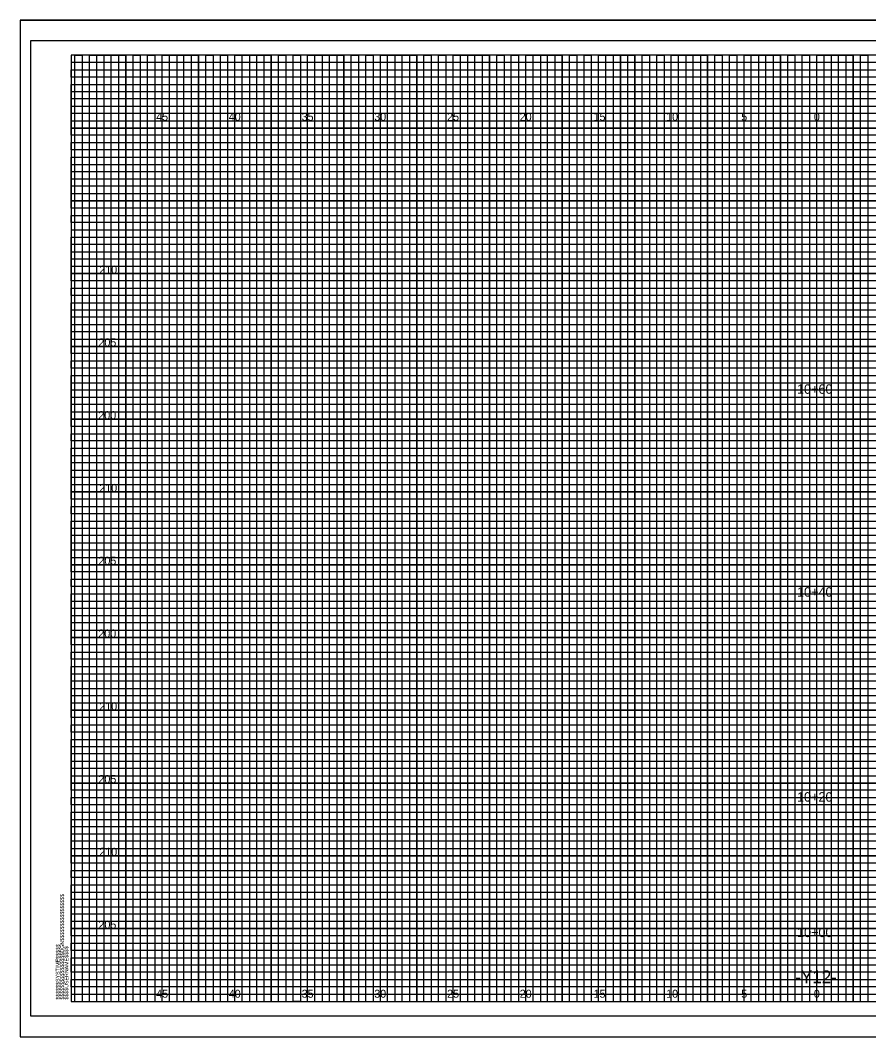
# Model space of a CAD drawing. Extents: x -4 to 103, y -2 to 138.
# Drawn here: x -3.5 to 54.8, y -2.4 to 67.4 of the extents above; entities that cross this region are included whole.
import ezdxf

# ---------------------------------------------------------------- set-up
doc = ezdxf.new("R2010")
doc.units = 0
for name, color, linetype in [('Exist XS Ground Line', 7, 'Continuous'), ('Old_Level_10', 7, 'Continuous'), ('Old_Level_16', 7, 'Continuous'), ('Old_Level_3', 7, 'Continuous'), ('Old_Level_5', 7, 'Continuous'), ('Old_Level_8', 7, 'Continuous'), ('Prop XS Dump Level', 7, 'Continuous'), ('Prop XS Elevation Labels', 7, 'Continuous'), ('Prop XS EOT Tick Mark', 7, 'Continuous'), ('Prop XS Finish Grade', 7, 'Continuous'), ('Prop XS Suitable Common Exc Shape', 7, 'Continuous')]:
    doc.layers.add(name, color=color, linetype=linetype)

msp = doc.modelspace()

# ---------------------------------------------------------------- linework, layer by layer
at = {"layer": 'Exist XS Ground Line'}
msp.add_lwpolyline([(103, 66), (-2.8, 66), (-2.8, -1), (103, -1)], close=True, dxfattribs=at)
at = {"layer": 'Old_Level_10'}
for p, q in [((1.25, 0), (1.25, 65)), ((3.75, 0), (3.75, 65)), ((6.25, 0), (6.25, 65)), ((8.75, 0), (8.75, 65)), ((11.25, 0), (11.25, 65)), ((13.75, 0), (13.75, 65)), ((16.25, 0), (16.25, 65)), ((18.75, 0), (18.75, 65)), ((21.25, 0), (21.25, 65)), ((23.75, 0), (23.75, 65)), ((26.25, 0), (26.25, 65)), ((28.75, 0), (28.75, 65)), ((31.25, 0), (31.25, 65)), ((33.75, 0), (33.75, 65)), ((36.25, 0), (36.25, 65)), ((38.75, 0), (38.75, 65)), ((41.25, 0), (41.25, 65)), ((43.75, 0), (43.75, 65)), ((46.25, 0), (46.25, 65)), ((48.75, 0), (48.75, 65)), ((51.25, 0), (51.25, 65)), ((53.75, 0), (53.75, 65)), ((0, 62.5), (74.25, 62.5)), ((0, 60), (102.5, 60)), ((0, 57.5), (102.5, 57.5)), ((0, 55), (102.5, 55)), ((0, 52.5), (102.5, 52.5)), ((0, 50), (102.5, 50)), ((0, 47.5), (102.5, 47.5)), ((0, 45), (102.5, 45)), ((0, 42.5), (102.5, 42.5)), ((0, 40), (102.5, 40)), ((0, 37.5), (102.5, 37.5)), ((0, 35), (102.5, 35)), ((0, 32.5), (102.5, 32.5)), ((0, 30), (102.5, 30)), ((0, 27.5), (102.5, 27.5)), ((0, 25), (102.5, 25)), ((0, 22.5), (102.5, 22.5)), ((0, 20), (102.5, 20)), ((0, 17.5), (102.5, 17.5)), ((0, 15), (102.5, 15)), ((0, 12.5), (102.5, 12.5)), ((0, 10), (102.5, 10)), ((0, 7.5), (102.5, 7.5)), ((0, 5), (102.5, 5)), ((0, 2.5), (102.5, 2.5))]:
    msp.add_line(p, q, dxfattribs=at)
at = {"layer": 'Old_Level_3'}
for p, q in [((-3.5, 67.4), (103.4, 67.4)), ((-3.5, 67.4), (-3.5, -2.425)), ((-3.5, -2.425), (103.4, -2.425))]:
    msp.add_line(p, q, dxfattribs=at)
at = {"layer": 'Old_Level_5'}
msp.add_lwpolyline([(103.4, 67.4), (-3.5, 67.4), (-3.5, -2.425), (103.4, -2.425)], close=True, dxfattribs=at)
at = {"layer": 'Old_Level_8'}
for points in [[(1.25, 0), (1.25, 65), (3.75, 65), (3.75, 0), (6.25, 0), (6.25, 65), (8.75, 65), (8.75, 0), (11.25, 0), (11.25, 65), (13.75, 65), (13.75, 0), (16.25, 0), (16.25, 65), (18.75, 65), (18.75, 0), (21.25, 0), (21.25, 65), (23.75, 65), (23.75, 0), (26.25, 0), (26.25, 65), (28.75, 65), (28.75, 0), (31.25, 0), (31.25, 65), (33.75, 65), (33.75, 0), (36.25, 0), (36.25, 65), (38.75, 65), (38.75, 0), (41.25, 0), (41.25, 65), (43.75, 65), (43.75, 0), (46.25, 0), (46.25, 65), (48.75, 65), (48.75, 0), (51.25, 0), (51.25, 65), (53.75, 65), (53.75, 0)], [(102.5, 60), (0, 60), (0, 62.5), (74.25, 62.5)], [(102.5, 55), (0, 55), (0, 57.5), (102.5, 57.5)], [(102.5, 50), (0, 50), (0, 52.5), (102.5, 52.5)], [(102.5, 45), (0, 45), (0, 47.5), (102.5, 47.5)], [(102.5, 40), (0, 40), (0, 42.5), (102.5, 42.5)], [(102.5, 35), (0, 35), (0, 37.5), (102.5, 37.5)], [(102.5, 30), (0, 30), (0, 32.5), (102.5, 32.5)], [(102.5, 25), (0, 25), (0, 27.5), (102.5, 27.5)], [(102.5, 20), (0, 20), (0, 22.5), (102.5, 22.5)], [(102.5, 15), (0, 15), (0, 17.5), (102.5, 17.5)], [(102.5, 10), (0, 10), (0, 12.5), (102.5, 12.5)], [(102.5, 5), (0, 5), (0, 7.5), (102.5, 7.5)], [(0, 2.5), (102.5, 2.5)]]:
    msp.add_lwpolyline(points, dxfattribs=at)
at = {"layer": 'Prop XS Elevation Labels'}
msp.add_lwpolyline([(102.5, 65), (0, 65), (0, 0), (102.5, 0)], close=True, dxfattribs=at)
at = {"layer": 'Prop XS Finish Grade'}
for points in [[(0.25, 0), (0.25, 65), (0.75, 65), (0.75, 0), (1.75, 0), (1.75, 65), (2.25, 65), (2.25, 0), (2.75, 0), (2.75, 65), (3.25, 65), (3.25, 0), (4.25, 0), (4.25, 65), (4.75, 65), (4.75, 0), (5.25, 0), (5.25, 65), (5.75, 65), (5.75, 0), (6.75, 0), (6.75, 65), (7.25, 65), (7.25, 0), (7.75, 0), (7.75, 65), (8.25, 65), (8.25, 0), (9.25, 0), (9.25, 65), (9.75, 65), (9.75, 0), (10.25, 0), (10.25, 65), (10.75, 65), (10.75, 0), (11.75, 0), (11.75, 65), (12.25, 65), (12.25, 0), (12.75, 0), (12.75, 65), (13.25, 65), (13.25, 0), (14.25, 0), (14.25, 65), (14.75, 65), (14.75, 0), (15.75, 0), (15.25, 0), (15.25, 65), (15.75, 65), (15.75, 0), (16.75, 0), (16.75, 65), (17.25, 65), (17.25, 0), (17.75, 0), (17.75, 65), (18.25, 65), (18.25, 0), (19.25, 0), (19.25, 65), (19.75, 65), (19.75, 0), (20.25, 0), (20.25, 65), (20.75, 65), (20.75, 0), (21.75, 0), (21.75, 65), (22.25, 65), (22.25, 0), (22.75, 0), (22.75, 65), (23.25, 65), (23.25, 0), (24.25, 0), (24.25, 65), (24.75, 65), (24.75, 0), (25.25, 0), (25.25, 65), (25.75, 65), (25.75, 0), (26.75, 0), (26.75, 65), (27.25, 65), (27.25, 0), (27.75, 0), (27.75, 65), (28.25, 65), (28.25, 0), (29.25, 0), (29.25, 65), (29.75, 65), (29.75, 0), (30.25, 0), (30.25, 65), (30.75, 65), (30.75, 0)], [(30.75, 0), (31.75, 0), (31.75, 65), (32.25, 65), (32.25, 0), (32.75, 0), (32.75, 65), (33.25, 65), (33.25, 0), (34.25, 0), (34.25, 65), (34.75, 65), (34.75, 0), (35.25, 0), (35.25, 65), (35.75, 65), (35.75, 0), (36.75, 0), (36.75, 65), (37.25, 65), (37.25, 0), (37.75, 0), (37.75, 65), (37.75, 0)], [(38.25, 65), (38.25, 0), (39.25, 0), (39.25, 65), (39.75, 65), (39.75, 0), (40.25, 0), (40.25, 65), (40.75, 65), (40.75, 0), (41.75, 0), (41.75, 65), (42.25, 65), (42.25, 0), (42.75, 0), (42.75, 65), (43.25, 65), (43.25, 0), (43.75, 0), (44.25, 0), (44.25, 65), (44.75, 65), (44.75, 0), (45.25, 0), (45.25, 65), (45.75, 65), (45.75, 0), (46.75, 0), (46.75, 65), (47.25, 65), (47.25, 0), (47.75, 0), (47.75, 65), (48.25, 65), (48.25, 0), (49.25, 0), (49.25, 65), (49.75, 65), (49.75, 0), (50.25, 0), (50.25, 65), (50.75, 65), (50.75, 0), (51.75, 0), (51.75, 65), (52.25, 65), (52.25, 0), (52.75, 0), (52.75, 65), (53.25, 65), (53.25, 0), (54.25, 0), (54.25, 65), (54.75, 65), (54.75, 0), (55.25, 0)], [(0, 62), (0, 63), (74.25, 63), (74.25, 63.5), (0, 63.5), (0, 64), (74.25, 64), (74.25, 64.5), (0, 64.5)], [(102.5, 62), (0, 62)], [(102.5, 61), (0, 61), (0, 61.5), (102.5, 61.5)], [(102.5, 59.5), (0, 59.5), (0, 60.5), (102.5, 60.5)], [(102.5, 58.5), (0, 58.5), (0, 59), (102.5, 59)], [(102.5, 57), (0, 57), (0, 58), (102.5, 58)], [(102.5, 56), (0, 56), (0, 56.5), (102.5, 56.5)], [(102.5, 54.5), (0, 54.5), (0, 55.5), (102.5, 55.5)], [(102.5, 53.5), (0, 53.5), (0, 54), (102.5, 54)], [(0, 53), (102.5, 53)], [(102.5, 52), (0, 52)], [(102.5, 51), (0, 51), (0, 51.5), (102.5, 51.5)], [(102.5, 49.5), (0, 49.5), (0, 50.5), (102.5, 50.5)], [(102.5, 48.5), (0, 48.5), (0, 49), (102.5, 49)], [(102.5, 47), (0, 47), (0, 48), (102.5, 48)], [(102.5, 46), (0, 46), (0, 46.5), (102.5, 46.5)], [(102.5, 44.5), (0, 44.5), (0, 45.5), (102.5, 45.5)], [(102.5, 43.5), (0, 43.5), (0, 44), (102.5, 44)], [(102.5, 42), (0, 42), (0, 43), (102.5, 43)], [(102.5, 41), (0, 41), (0, 41.5), (102.5, 41.5)], [(102.5, 39.5), (0, 39.5), (0, 40.5), (102.5, 40.5)], [(102.5, 38.5), (0, 38.5), (0, 39), (102.5, 39)], [(102.5, 37), (0, 37), (0, 38), (102.5, 38)], [(102.5, 36), (0, 36), (0, 36.5), (102.5, 36.5)], [(102.5, 34.5), (0, 34.5), (0, 35.5), (102.5, 35.5)], [(102.5, 33.5), (0, 33.5), (0, 34), (102.5, 34)], [(102.5, 32), (0, 32), (0, 33), (102.5, 33)], [(102.5, 31), (0, 31), (0, 31.5)], [(0, 31.5), (102.5, 31.5)], [(102.5, 29.5), (0, 29.5), (0, 30.5), (102.5, 30.5)], [(102.5, 28.5), (0, 28.5), (0, 29), (102.5, 29)], [(102.5, 27), (0, 27), (0, 28), (102.5, 28)], [(102.5, 26), (0, 26), (0, 26.5), (102.5, 26.5)], [(102.5, 24.5), (0, 24.5), (0, 25.5), (102.5, 25.5)], [(102.5, 23.5), (0, 23.5), (0, 24), (102.5, 24)], [(102.5, 22), (0, 22), (0, 23), (102.5, 23)], [(102.5, 21), (0, 21), (0, 21.5), (102.5, 21.5)], [(102.5, 19.5), (0, 19.5), (0, 20.5), (102.5, 20.5)], [(102.5, 18.5), (0, 18.5), (0, 19), (102.5, 19)], [(102.5, 17), (0, 17), (0, 18), (102.5, 18)], [(102.5, 16), (0, 16), (0, 16.5), (102.5, 16.5)], [(102.5, 14.5), (0, 14.5), (0, 15.5), (102.5, 15.5)], [(102.5, 13.5), (0, 13.5), (0, 14), (102.5, 14)], [(102.5, 12), (0, 12), (0, 13), (102.5, 13)], [(102.5, 11), (0, 11), (0, 11.5), (102.5, 11.5)], [(102.5, 9.5), (0, 9.5), (0, 10.5), (102.5, 10.5)], [(102.5, 8.5), (0, 8.5), (0, 9), (102.5, 9)], [(102.5, 7), (0, 7), (0, 8), (102.5, 8)], [(102.5, 6), (0, 6), (0, 6.5), (102.5, 6.5)], [(102.5, 4.5), (0, 4.5), (0, 5.5), (102.5, 5.5)], [(102.5, 3.5), (0, 3.5), (0, 4), (102.5, 4)], [(102.5, 2), (0, 2), (0, 3), (102.5, 3)], [(102.5, 1), (0, 1), (0, 1.5), (102.5, 1.5)], [(0, 0.5), (102.5, 0.5)]]:
    msp.add_lwpolyline(points, dxfattribs=at)

# ---------------------------------------------------------------- texts
at = {"layer": 'Old_Level_16'}
for s, p in [('45', (5.84, 60.5)), ('40', (10.831, 60.5)), ('35', (15.84, 60.5)), ('30', (20.831, 60.5)), ('25', (25.84, 60.5)), ('20', (30.831, 60.5)), ('15', (35.906, 60.5)), ('10', (40.897, 60.5)), ('5', (46.057, 60.5)), ('0', (51.049, 60.5)), ('0', (51.049, 60.5)), ('45', (5.84, 0.25)), ('40', (10.831, 0.25)), ('35', (15.84, 0.25)), ('30', (20.831, 0.25)), ('25', (25.84, 0.25)), ('20', (30.831, 0.25)), ('15', (35.906, 0.25)), ('10', (40.897, 0.25)), ('5', (46.057, 0.25)), ('0', (51.049, 0.25)), ('0', (51.049, 0.25))]:
    msp.add_text(s, height=0.55, dxfattribs=at).set_placement(p)
at = {"layer": 'Old_Level_8'}
msp.add_text('040397', height=0.0025, rotation=90, dxfattribs=at).set_placement((-0.001, 64.986))
at = {"layer": 'Prop XS Dump Level'}
for s, p in [('210', (1.93, 50)), ('205', (1.872, 45)), ('200', (1.864, 40)), ('210', (1.93, 35)), ('205', (1.872, 30)), ('200', (1.864, 25)), ('210', (1.93, 20)), ('205', (1.872, 15)), ('210', (1.93, 10)), ('205', (1.872, 5))]:
    msp.add_text(s, height=0.55, dxfattribs=at).set_placement(p)
at = {"layer": 'Prop XS Elevation Labels'}
for s, p in [('$$$$$$$$$$$$$$$$DGN$$$$$$$$$$$$$$$$', (-0.5, 0.125)), ('$$$$$$SYSTIME$$$$$', (-0.797, 0.125)), ('$$$$USERNAME$$$$', (-0.2, 0.125))]:
    msp.add_text(s, height=0.2625, rotation=90, dxfattribs=at).set_placement(p)
at = {"layer": 'Prop XS EOT Tick Mark'}
msp.add_text('-Y12-', height=0.875, dxfattribs=at).set_placement((49.773, 1.25))
at = {"layer": 'Prop XS Suitable Common Exc Shape'}
for s, p in [('10+60', (49.893, 41.741)), ('10+40', (49.893, 27.802)), ('10+20', (49.893, 13.72)), ('10+00', (49.893, 4.416))]:
    msp.add_text(s, height=0.65, dxfattribs=at).set_placement(p)

doc.saveas('drawing.dxf')
